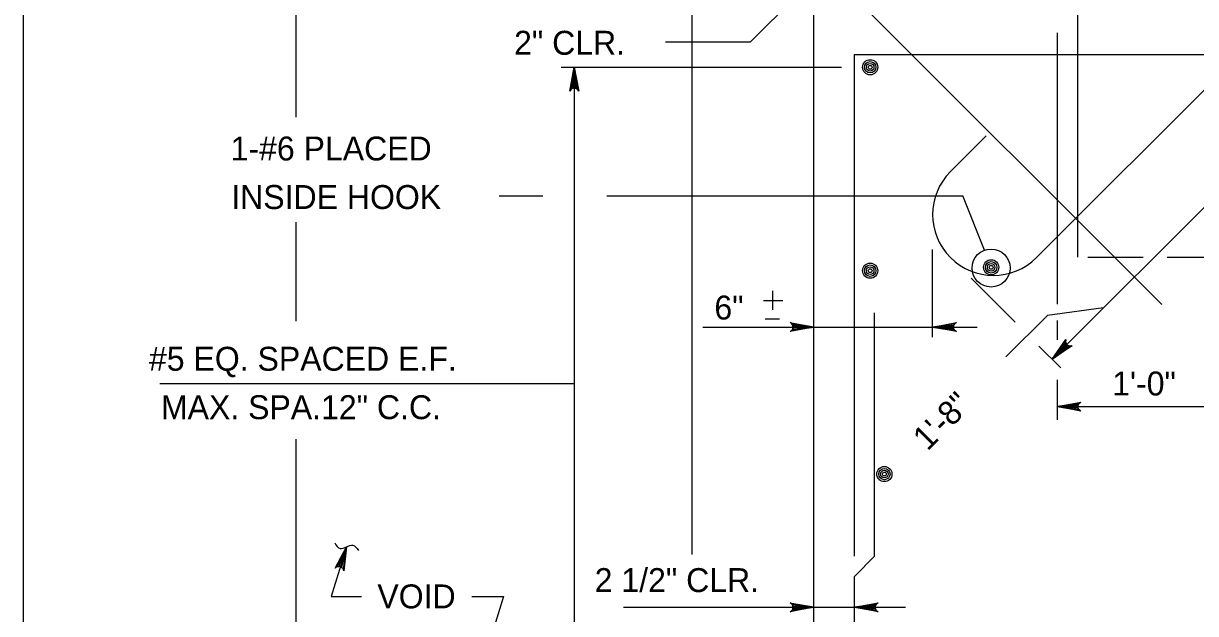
# Model space of a CAD drawing. Extents: x 638653 to 642302, y 298557 to 300414.
# Drawn here: x 639863.2 to 640010, y 299539 to 299612.9 of the extents above; entities that cross this region are included whole.
import ezdxf

# ---------------------------------------------------------------- set-up
doc = ezdxf.new("R2010")
doc.units = 0
doc.layers.add('1', color=7, linetype='Continuous')

msp = doc.modelspace()

# ---------------------------------------------------------------- linework, layer by layer
at = {"layer": '1'}
for p, q in [((639863.16, 299165.52), (639863.16, 299729.52)), ((639995.23, 299651.63), (639995.23, 299583.63)), ((640005.79, 299577.71), (639933.16, 299650.34)), ((639990.09, 299583.57), (640053.02, 299646.5)), ((639946.97, 299546.36), (639946.97, 299630.62)), ((639897.28, 299624.56), (639897.28, 299601.17)), ((639967.18, 299623.5), (639954.28, 299610.6)), ((639962.21, 299510.6), (639962.21, 299614.11)), ((639992.69, 299611.72), (639992.69, 299577.72)), ((639943.6, 299610.6), (639954.28, 299610.6)), ((639967.29, 299609.03), (640018.09, 299609.03)), ((639967.29, 299546.16), (639967.29, 299609.03)), ((639930.52, 299607.42), (639965.66, 299607.42)), ((639932.18, 299607.42), (639932.18, 299530.84)), ((640028, 299606.74), (639992.07, 299570.82)), ((639979.32, 299594.35), (639983.81, 299598.84)), ((639922.79, 299591.31), (639928.24, 299591.31)), ((639936.28, 299591.31), (639980.86, 299591.31)), ((639983.57, 299584.48), (639980.86, 299591.31)), ((639897.28, 299588.02), (639897.28, 299575.59)), ((639977.09, 299573.58), (639977.09, 299584.57)), ((639996.55, 299583.63), (640003.48, 299583.63)), ((640006.46, 299583.63), (640033.93, 299583.63)), ((639987.42, 299575.47), (639981.92, 299580.98)), ((639957.07, 299577.04), (639957.07, 299579.4)), ((639955.91, 299578.19), (639958.32, 299578.19)), ((639956.1, 299575.91), (639957.9, 299575.91)), ((639969.82, 299546.16), (639969.82, 299576.64)), ((639991.47, 299576.33), (639986.28, 299571.14)), ((639998.51, 299577.26), (639991.47, 299576.33)), ((639948.3, 299574.86), (639982.66, 299574.86)), ((639992.69, 299575.68), (639992.69, 299573.27)), ((639993.14, 299569.75), (639990.4, 299572.49)), ((639880.23, 299567.81), (639932.18, 299567.81)), ((639992.69, 299568.26), (639992.69, 299563.22)), ((639992.69, 299564.89), (640023.17, 299564.89)), ((639897.28, 299560.8), (639897.28, 299526.74)), ((639903.64, 299547.32), (639901.72, 299541.11)), ((639969.82, 299546.16), (639967.29, 299543.62)), ((639967.29, 299513.78), (639967.29, 299543.62)), ((639901.72, 299541.11), (639905.51, 299541.11)), ((639919.35, 299541.11), (639923.33, 299541.11)), ((639923.33, 299541.11), (639921.41, 299534.9)), ((639938.36, 299539.74), (639973.7, 299539.74))]:
    msp.add_line(p, q, dxfattribs=at)
for points in [[(639932.18, 299607.42), (639932.74, 299604.44), (639932.66, 299604.55), (639932.58, 299604.67), (639932.48, 299604.73), (639932.38, 299604.79), (639932.28, 299604.8), (639932.18, 299604.82), (639932.08, 299604.8), (639931.98, 299604.79), (639931.88, 299604.73), (639931.78, 299604.67), (639931.7, 299604.55), (639931.62, 299604.44), (639932.18, 299607.42), (639931.7, 299604.55), (639931.78, 299604.67), (639932.18, 299607.42), (639931.88, 299604.73), (639931.98, 299604.79), (639932.18, 299607.42), (639932.08, 299604.8), (639932.18, 299604.82), (639932.18, 299607.42), (639932.28, 299604.8), (639932.38, 299604.79), (639932.18, 299607.42), (639932.48, 299604.73), (639932.58, 299604.67), (639932.18, 299607.42), (639932.66, 299604.55)], [(639962.21, 299574.86), (639959.22, 299574.3), (639959.34, 299574.38), (639959.45, 299574.46), (639959.51, 299574.56), (639959.57, 299574.66), (639959.59, 299574.76), (639959.61, 299574.86), (639959.59, 299574.96), (639959.57, 299575.06), (639959.51, 299575.16), (639959.45, 299575.26), (639959.34, 299575.34), (639959.22, 299575.42), (639962.21, 299574.86), (639959.34, 299575.34), (639959.45, 299575.26), (639962.21, 299574.86), (639959.51, 299575.16), (639959.57, 299575.06), (639962.21, 299574.86), (639959.59, 299574.96), (639959.61, 299574.86), (639962.21, 299574.86), (639959.59, 299574.76), (639959.57, 299574.66), (639962.21, 299574.86), (639959.51, 299574.56), (639959.45, 299574.46), (639962.21, 299574.86), (639959.34, 299574.38)], [(639977.09, 299574.86), (639980.07, 299575.42), (639979.96, 299575.34), (639979.84, 299575.26), (639979.78, 299575.16), (639979.72, 299575.06), (639979.71, 299574.96), (639979.69, 299574.86), (639979.71, 299574.76), (639979.72, 299574.66), (639979.78, 299574.56), (639979.84, 299574.46), (639979.96, 299574.38), (639980.07, 299574.3), (639977.09, 299574.86), (639979.96, 299574.38), (639979.84, 299574.46), (639977.09, 299574.86), (639979.78, 299574.56), (639979.72, 299574.66), (639977.09, 299574.86), (639979.71, 299574.76), (639979.69, 299574.86), (639977.09, 299574.86), (639979.71, 299574.96), (639979.72, 299575.06), (639977.09, 299574.86), (639979.78, 299575.16), (639979.84, 299575.26), (639977.09, 299574.86), (639979.96, 299575.34)], [(639992.07, 299570.82), (639993.79, 299573.32), (639993.76, 299573.18), (639993.74, 299573.05), (639993.77, 299572.93), (639993.8, 299572.82), (639993.85, 299572.74), (639993.91, 299572.66), (639994, 299572.6), (639994.08, 299572.54), (639994.19, 299572.51), (639994.3, 299572.48), (639994.44, 299572.51), (639994.58, 299572.53), (639992.07, 299570.82), (639994.44, 299572.51), (639994.3, 299572.48), (639992.07, 299570.82), (639994.19, 299572.51), (639994.08, 299572.54), (639992.07, 299570.82), (639994, 299572.6), (639993.91, 299572.66), (639992.07, 299570.82), (639993.85, 299572.74), (639993.8, 299572.82), (639992.07, 299570.82), (639993.77, 299572.93), (639993.74, 299573.05), (639992.07, 299570.82), (639993.76, 299573.18)], [(639992.69, 299564.89), (639995.67, 299565.45), (639995.56, 299565.37), (639995.44, 299565.29), (639995.38, 299565.19), (639995.32, 299565.09), (639995.3, 299564.99), (639995.29, 299564.89), (639995.3, 299564.79), (639995.32, 299564.69), (639995.38, 299564.59), (639995.44, 299564.49), (639995.56, 299564.41), (639995.67, 299564.33), (639992.69, 299564.89), (639995.56, 299564.41), (639995.44, 299564.49), (639992.69, 299564.89), (639995.38, 299564.59), (639995.32, 299564.69), (639992.69, 299564.89), (639995.3, 299564.79), (639995.29, 299564.89), (639992.69, 299564.89), (639995.3, 299564.99), (639995.32, 299565.09), (639992.69, 299564.89), (639995.38, 299565.19), (639995.44, 299565.29), (639992.69, 299564.89), (639995.56, 299565.37)], [(639903.64, 299547.32), (639903.29, 299544.31), (639903.21, 299544.57), (639903.05, 299544.75), (639902.87, 299544.84), (639902.67, 299544.86), (639902.44, 299544.81), (639902.22, 299544.64), (639903.64, 299547.32), (639902.44, 299544.81), (639902.67, 299544.86), (639903.64, 299547.32), (639902.87, 299544.84), (639903.05, 299544.75), (639903.64, 299547.32), (639903.21, 299544.57)], [(639962.21, 299539.74), (639959.22, 299539.18), (639959.34, 299539.26), (639959.45, 299539.34), (639959.51, 299539.44), (639959.57, 299539.54), (639959.59, 299539.64), (639959.61, 299539.74), (639959.59, 299539.84), (639959.57, 299539.94), (639959.51, 299540.04), (639959.45, 299540.14), (639959.34, 299540.22), (639959.22, 299540.3), (639962.21, 299539.74), (639959.34, 299540.22), (639959.45, 299540.14), (639962.21, 299539.74), (639959.51, 299540.04), (639959.57, 299539.94), (639962.21, 299539.74), (639959.59, 299539.84), (639959.61, 299539.74), (639962.21, 299539.74), (639959.59, 299539.64), (639959.57, 299539.54), (639962.21, 299539.74), (639959.51, 299539.44), (639959.45, 299539.34), (639962.21, 299539.74), (639959.34, 299539.26)], [(639967.29, 299539.74), (639970.27, 299540.3), (639970.15, 299540.22), (639970.04, 299540.14), (639969.98, 299540.04), (639969.92, 299539.94), (639969.9, 299539.84), (639969.89, 299539.74), (639969.9, 299539.64), (639969.92, 299539.54), (639969.98, 299539.44), (639970.04, 299539.34), (639970.15, 299539.26), (639970.27, 299539.18), (639967.29, 299539.74), (639970.15, 299539.26), (639970.04, 299539.34), (639967.29, 299539.74), (639969.98, 299539.44), (639969.92, 299539.54), (639967.29, 299539.74), (639969.9, 299539.64), (639969.89, 299539.74), (639967.29, 299539.74), (639969.9, 299539.84), (639969.92, 299539.94), (639967.29, 299539.74), (639969.98, 299540.04), (639970.04, 299540.14), (639967.29, 299539.74), (639970.15, 299540.22)]]:
    msp.add_lwpolyline(points, dxfattribs=at)
for centre, radius in [((639969.26, 299607.42), 0.952), ((639969.26, 299607.42), 0.714), ((639969.26, 299607.42), 0.476), ((639969.26, 299607.42), 0.238), ((639984.41, 299582.26), 2.38), ((639984.42, 299582.35), 0.952), ((639969.26, 299581.93), 0.952), ((639969.26, 299581.93), 0.714), ((639969.26, 299581.93), 0.476), ((639969.26, 299581.93), 0.238), ((639984.42, 299582.35), 0.714), ((639984.42, 299582.35), 0.476), ((639984.42, 299582.35), 0.238), ((639971.04, 299556.44), 0.952), ((639971.04, 299556.44), 0.714), ((639971.04, 299556.44), 0.476), ((639971.04, 299556.44), 0.238)]:
    msp.add_circle(centre, radius, dxfattribs=at)
msp.add_arc((639984.71, 299588.96), 7.62, 135, 315, dxfattribs=at)
msp.add_spline([(639902.16, 299547.81), (639902.85, 299547.12), (639904.44, 299547.53), (639905.13, 299546.88)], degree=3, dxfattribs=at)

# ---------------------------------------------------------------- texts
for s, p in [('2" CLR.', (639924.64, 299608.99)), ('1-#6 PLACED', (639889.12, 299595.74)), ('INSIDE HOOK', (639889.2, 299589.66)), ('6"', (639949.74, 299575.81)), ('#5 EQ. SPACED E.F.', (639878.89, 299569.39)), ('1\'-0"', (639999.58, 299566.29)), ('MAX. SPA.12" C.C.', (639880.39, 299563.32)), ('2 1/2" CLR.', (639934.74, 299541.65)), ('VOID', (639907.51, 299539.61))]:
    msp.add_text(s, height=3, dxfattribs=at).set_placement(p)
msp.add_text('1\'-8"', height=3, rotation=45, dxfattribs=at).set_placement((639976.44, 299559.23))

doc.saveas('drawing.dxf')
